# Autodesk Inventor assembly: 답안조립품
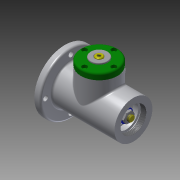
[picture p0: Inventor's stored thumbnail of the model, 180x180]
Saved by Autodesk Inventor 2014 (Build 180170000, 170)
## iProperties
Created: 2016-08
Part Number: 답안조립품
Document SubType Name: Assembly
Designer: owner
Author: owner
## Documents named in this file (16)
- C:\Users\owner\Desktop\460807V1006\답안조립품.iam
- C:\Users\owner\Desktop\460807V1006\본체.ipt
- C:\Users\owner\Desktop\460807V1006\베어링 15 x 35 x 11.ipt
- C:\Users\owner\Desktop\460807V1006\부시1.ipt
- C:\Users\owner\Desktop\460807V1006\편심축.ipt
- C:\Users\owner\Desktop\460807V1006\멈춤링 35x1.6.ipt
- C:\Users\owner\Desktop\460807V1006\링크.ipt
- C:\Users\owner\Desktop\460807V1006\슬라이더.ipt
- C:\Users\owner\Desktop\460807V1006\클래스터 핀 6 x 24.ipt
- C:\Users\owner\Desktop\460807V1006\부시2.ipt
- C:\Users\owner\Desktop\460807V1006\와셔 10x21.ipt
- C:\Users\owner\Desktop\460807V1006\너트 M10.ipt
- C:\Users\owner\Desktop\460807V1006\멈춤링 15 x 1.ipt
- C:\Users\owner\Desktop\460807V1006\탑 커버.ipt
- 탑 커버.ipt
- C:\Users\owner\Desktop\460807V1006\탑 부시.ipt
